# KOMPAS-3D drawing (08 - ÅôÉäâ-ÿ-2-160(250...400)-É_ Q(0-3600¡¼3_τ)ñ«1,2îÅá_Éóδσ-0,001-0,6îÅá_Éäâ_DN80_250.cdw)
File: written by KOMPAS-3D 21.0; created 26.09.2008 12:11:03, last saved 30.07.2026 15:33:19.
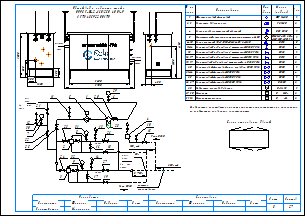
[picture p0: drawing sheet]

Sheets 1-2: A3, landscape

Document properties: Наименование: Макро:21; Автор: RaskoAdmin; Форматы листов документа: 2xA3; Полное имя файла: \\ur38nt01\Departments\КТО\КБ ПУРДГ\Заявки\Прайс-лист на типовые шкафы ГРПШ\ПУРДГ_стандарт_30_04_2026\ПУРДГ с РДГ(Н, В)\ПУРДГ-Ш-2-160(250...400)-Р_ Q(0-3600нм3_ч)до1,2МПа_Рвых-0,001-0,6МПа_РДГ_DN80_250.cdw

Title block, sheet 1: Наименование: Пункт учета газа / ПУГ-Ш-400-Р / ЛГТИ.485922.001ТУ; designation: ЛГТИ.03.4411141; sheet number: 1; Количество листов документа: 2; organisation: ООО "ЭЛЬСТЕР Газэлектроника"; Форматы листов документа: A3; stored path: C:\Рабочие документы\Компас\ПУГ\Схема.cdw; Разработал: Устинов; Проверил: Кошкин; Утвердил: Кошкин
Title block, sheet 2: sheet number: 2; stored path: D:\Рабочие документы\Заявки\ПУРДГ\ПУРДГ-ШУЭО-2-100-Р 4411220.cdw; designation, second copy: ЛГТИ.03.4411141-

Views: Вид 1, Вид 2
Referenced files: wcvoit.frw
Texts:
  Normal
  № на
  схеме
  Усл.
  обозн.
  Марка
  (модель)
  Кол.
  Фильтр газовый фланцевый
  ФГ 16-80
  Регулятор давления газа
  РДГ-50
  Клапан предохранительный сбросной
  ПСК DN25
  Измерительный комплекс с ротационным счетчиком Ду50
  СГ-ЭК-Р-(0,2...2,0)-
  Кран кнопочный VE-РАСКО-НЗ-1,6-G1/2-М20
  DN15
  Кран шаровой "под приварку" штуцерный DN20 PN16
  Кран шаровой "под приварку" штуцерный DN25 PN16
  DN20
  DN25
  Кран шаровой "под приварку" штуцерный DN15 PN16
  Кран шаровой "под приварку" штуцерный п/п DN20 PN16
  Кран шаровой фланцевый с мех. приводом DN80 PN16
  Кран шаровой фланцевый DN50 PN16
  Кран шаровой фланцевый DN80 PN16
  Кран шаровой фланцевый DN250 PN16
  DN80
  DN50
  DN250
  Индикатор перепада давления
  Манометр
  Манометр-напоромер
  Delta 15
  0...     МПа
  0...     кПа
  Общий вид и габариты шкафа
  ПУРДГ-Ш-2-160(250...400)-Р
  Выход газа
  Вход газа
  logo-rasko-ge.png
  DN 1
  местное
  сопротивление
  Римп DN20
  Выход
  газа
  Р=     кПа
  Вход
  Р=       МПа
  PDI
  Схема открывания дверей
  Предприятие изготовитель может заменять комплектующие на аналогичные,
  не ухудшающие заявленных характеристик.
  Должность
  Конструктор
  Фамилия
  Подпись
  Дата
  Согласовано
  Максимкин
  Лист
  Листов
  POLYLINE_STYLE_0.18_RGB_0_0_0
  POLYLINE_STYLE_0.50_RGB_0_0_0
  POLYLINE_STYLE_0.34_RGB_0_0_0
  PHANTOM_RGB_0_0_0_SC_1_THICK_0.18
  K5LT_THIN_RGB_0_0_0_THICK_0.18
  K5LT32769_RGB_0_0_0_THICK_0.18
  K5LT12_RGB_0_0_0_SC_1_THICK_0.18
  K5LT_DASHED_RGB_0_0_0_SC_1_THICK_0.18
  ACISOTGL_RGB_0_0_0_SC_0.8_THICK_0.25
  CONTINUOUS_RGB_0_127_31_THICK_0.3
  CONTINUOUS_RGB_0_0_255_THICK_0.35
  CONTINUOUS_RGB_255_0_0_THICK_0.35
  POLYLINE_STYLE_0.25_RGB_0_0_0
  CONTINUOUS_RGB_0_0_0_THICK_0.5
  POLYLINE_STYLE_0.35_RGB_0_0_255
  CONTINUOUS_RGB_0_0_0_THICK_0.4
  CONTINUOUS_RGB_0_0_0_THICK_0.35
  НЕВИДИМАЯ_RGB_0_0_0_SC_0.3_THICK_0.25
  СONTINUOUS_RGB_0_0_0_THICK_0.25
  ОСЕВАЯ2_RGB_248_153_30_SC_0.3_THICK_0.25
  Без оформления
Dimensions and other numbers on the sheet: 1; 2, 3; 2; 4; 5; -160 (250; 400)/1,6; 6-10; 11-14; 15; 16, 17; 18, 19; 20; 21-24; 25; 26, 27; 28; 29, 30; 31, 32; 1500; 450; 500; 1200; 550; 305; 3600; 4130; 2000; 3900; 5,,,7DN 1; 7; 30; 12; 21; 22; 11; 6; 29; 23; 31; 8; 13; 26; 18; 10; 24; 32; 9; 3; 14; 27; 19; 16; 17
